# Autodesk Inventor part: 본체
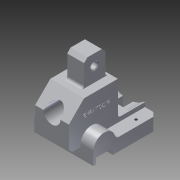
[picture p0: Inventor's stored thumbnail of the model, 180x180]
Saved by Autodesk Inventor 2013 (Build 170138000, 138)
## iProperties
Created: 2016-11
Part Number: 본체
Material: 알루미늄 6061
Document SubType Name: Modeling
Designer: 나래
Density: 2.71 g/cm^3
Mass: 462.907 g
Surface Area: 317.29 cm^2
Volume: 170.814 cm^3
Author: 나래
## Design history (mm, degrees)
sketch "스케치1"
  geometry: L1 (20, 18)-(-20, 18); L2 (-20, 18)-(-20, -30); L3 (-20, -30)-(20, -30); L4 (20, -30)-(20, 18); 2 further points
  constraints: 8 end point, 2 parallel, 1 horizontal, 1 midpoint, 1 perpendicular, 1 vertical alignment
  dimensions: "d0" = 30 distance from line of L3 point (0, 0); "d1" = 48 distance of L3.end L1.start; "d2" = 40 distance of L1.start L1.end
extrude "돌출1" new body sketch "스케치1" stored distance "d3" = 58; taper "d4" = 0 deg
sketch "스케치2"
  geometry: L1 (-30, -29)-(-30, 29) reference; L2 (-30, -29)-(18, -29) reference; L3 (18, 29)-(-30, 29) reference; L4 (-27, 2)-(-42, 2); L5 (-42, -8)-(-42, -61); L6 (-42, -61)-(-27, -61); L7 (-27, -61)-(-27, -11); L8 (-27, 15)-(-42, 15); L9 (-42, 15)-(-42, 12); L10 (-42, 12)-(-35, 12); L11 (-35, 12)-(-35, -8); L12 (-35, -8)-(-42, -8); L13 (-27, -11)-(-27, 2); A1 r 13 centre (-27, 2) between (-27, -11) and (-27, 15); 1 further point
  constraints: 20 end point, 7 perpendicular, 3 parallel, 2 point on circle, 1 centre point, 1 coincident, 1 horizontal, 1 tangent, 1 other
  dimensions: "d5" = 90 distance between parallel lines of L6 L3; "d6" = 42 distance from line of L5 point (0, 0); "d7" = 15 distance between parallel lines of L5 L7; "d8" = 63 distance between parallel lines of L6 L4; "d9" = 13 radius of A1; "d11" = 3 distance between parallel lines of L8 L10; "d12" = 7 distance of L9.end L10.end; "d13" = 15 distance between parallel lines of L9 L7
extrude "돌출2" join sketch "스케치2" stored distance "d14" = 70; taper "d15" = 0 deg
sketch "스케치3"
  geometry: L1 (70, -15)-(0, -15) reference; L2 (15, -15)-(55, -15); L3 (55, -15)-(55, 5); L4 (55, 5)-(15, 5); L5 (15, 5)-(15, -15); L6 (35, 27)-(35, -15); L7 (15, 45)-(15, 0) reference; L8 (55, 0)-(55, 45) reference
  constraints: 10 end point, 2 parallel, 2 perpendicular, 2 point on line, 1 horizontal, 1 midpoint, 1 other
  dimensions: "d16" = 20 distance of L4.end L2.start
extrude "돌출3" join sketch "스케치3" distance "d18" = 50; taper "d19" = 0 deg
sketch "스케치4"
  geometry: L1 (70, 0)-(0, 0) reference; L2 (35, 42)-(35, 0); L3 (29, 13.627)-(29, 0); L4 (41, 13.627)-(41, 0); L5 (29, 0)-(41, 0); A1 r 29 centre (35, 42) between (41, 13.627) and (29, 13.627); 1 further point
  constraints: 8 end point, 2 parallel, 2 point on circle, 2 point on line, 1 centre point, 1 coincident, 1 collinear, 1 midpoint, 1 perpendicular, 1 other
  dimensions: "d20" = 29 radius of A1; "d22" = 12 distance between parallel lines of L4 L3
extrude "돌출4" cut sketch "스케치4" distance "d23" = 18; taper "d24" = 0 deg
chamfer "모따기1" distance "d25" = 18; stored, may be unused: second distance "d26" = 2, angle "d27" = 45 deg
chamfer "모따기2" distance "d28" = 4; stored, may be unused: second distance "d29" = 2, angle "d30" = 45 deg
sketch "스케치5"
  geometry: 1 further point
hole "구멍1" sketch "스케치5" at (0, 0) diameter "d31" = 20; stored, may be unused: countersink angle "d35" = 90 deg, drill point angle "d37" = 118 deg; dims "d32" = 6, "d33" = 29, "d34" = 7, "d36" = 8
sketch "스케치6"
  geometry: L1 (18, -29)-(18, 11) reference; L2 (14.5, -29)-(-14.5, -29) reference; L3 (18, -24)-(48, -24); L4 (48, -24)-(48, 1); L5 (48, 1)-(18, 1); L6 (18, 1)-(18, -24); L7 (-42, -61)-(-42, -8) reference; 1 further point
  constraints: 8 end point, 2 parallel, 1 horizontal, 1 perpendicular, 1 point on line
  dimensions: "d38" = 5 distance between parallel lines of L2 L3; "d39" = 25 distance of L3.end L4.end; "d43" = 90 distance between parallel lines of L7 L4
extrude "돌출5" join sketch "스케치6" stored distance "d41" = 20; taper "d42" = 0 deg
sketch "스케치7"
  geometry: L1 (-1, 48)-(-1, 18) reference; 2 further points
  dimensions: "d44" = 12.5 distance from line of L1 point (11.5, 35); "d45" = 35 vertical distance of point (0, 0) point (11.5, 35)
hole "구멍2" sketch "스케치7" at (11.5, 35) diameter "d46" = 8; stored, may be unused: countersink angle "d50" = 90 deg, drill point angle "d52" = 118 deg; dims "d47" = 6, "d48" = 29, "d49" = 7, "d51" = 8
chamfer "모따기3" distance "d53" = 4; stored, may be unused: second distance "d54" = 2, angle "d55" = 45 deg
chamfer "모따기4" distance "d56" = 1; stored, may be unused: second distance "d57" = 2, angle "d58" = 45 deg
fillet "모깎기1" dims "d59" = 5
node "작업 평면1"
sketch "스케치8"
  geometry: L1 (-70, -53)-(-55, -53) reference; L2 (-35, 8)-(-35, -53); 2 further points
  constraints: 2 end point, 1 perpendicular, 1 symmetric about line
  dimensions: "d61" = 18 distance from line of L1 point (-62.5, -35); "d62" = 55 distance of point (-7.5, -35) point (-62.5, -35)
hole "구멍3" sketch "스케치8" at (-7.5, -35), (-62.5, -35) diameter "d63" = 3.242; stored, may be unused: countersink angle "d67" = 90 deg, drill point angle "d69" = 118 deg; dims "d64" = 20, "d65" = 29, "d66" = 7, "d68" = 8
sketch "스케치9"
  geometry: L1 (44, 48)-(44, 8) reference; L2 (4, 48)-(44, 48) reference; 2 further points
  constraints: 1 other
  dimensions: "d70" = 18 distance from line of L2 point (19, 30); "d71" = 25 distance from line of L1 point (19, 30)
feature "엠보싱1" sketch "스케치9" dims "d0" = 30, "d1" = 48, "d2" = 40, "d72" = 0.5, "d73" = 0
fillet "모깎기2" dims "d74" = 3
chamfer "모따기5" distance "d75" = 5; stored, may be unused: second distance "d76" = 2, angle "d77" = 45 deg
node "솔리드1"
other parameters: "d60" = -15
